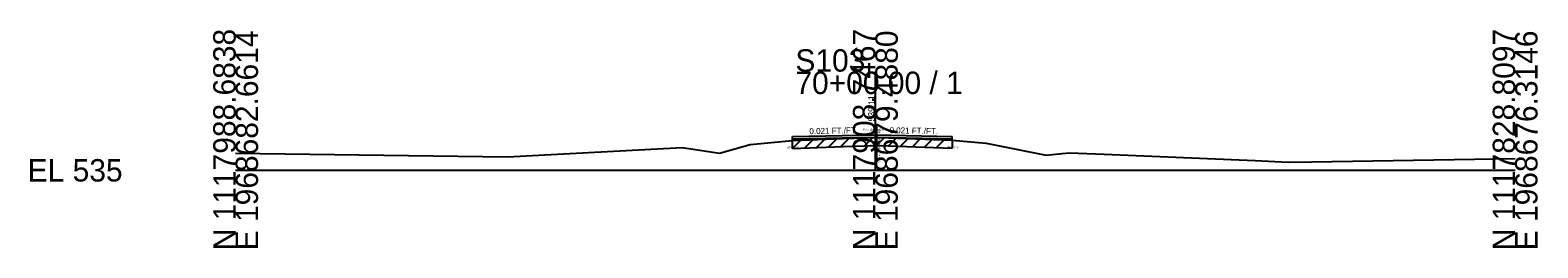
# Model space of a CAD drawing. Extents: x -26 to 163, y -10 to 24018.
# Drawn here: x -25.7 to 162.8, y 17990.3 to 18017.5 of the extents above; entities that cross this region are included whole.
import ezdxf

# ---------------------------------------------------------------- set-up
doc = ezdxf.new("R2010")
doc.units = 0
for name, color, linetype in [('RD_GPK_XS_Cell', 7, 'Continuous'), ('RD_XS_ExGround', 7, 'Continuous'), ('RD_XS_ExPaveRet', 7, 'Continuous'), ('RD_XS_Misc_Line', 7, 'Continuous'), ('RD_XS_PaveOvlay_CP', 7, 'Continuous'), ('RD_XS_TX_Elev_EX', 7, 'Continuous'), ('RD_XS_TX_ExEOP', 7, 'Continuous'), ('RD_XS_TX_Notes', 7, 'Continuous'), ('RD_XS_TX_Profile', 7, 'Continuous'), ('RD_XS_TX_Slope', 7, 'Continuous')]:
    doc.layers.add(name, color=color, linetype=linetype)

msp = doc.modelspace()

# ---------------------------------------------------------------- linework, layer by layer
at = {"layer": 'RD_GPK_XS_Cell'}
for p, q in [((80, 18000), (80, 18012.34)), ((0, 18000), (80, 18000)), ((80, 18000), (160, 18000))]:
    msp.add_line(p, q, dxfattribs=at)
at = {"layer": 'RD_XS_ExGround'}
msp.add_lwpolyline([(0, 18002.15), (33.98, 18001.68), (55.86, 18002.84), (60.51, 18002.13), (64.34, 18003.21), (69.63, 18003.74), (75.97, 18003.96), (80.14, 18004.11), (81.66, 18004.06), (89.61, 18003.77), (93.87, 18003.39), (101.36, 18001.89), (103.33, 18002.1), (104.26, 18002.2), (108.59, 18002.02), (127.49, 18001.22), (131.62, 18001.04), (134.56, 18001.08), (160, 18001.47)], dxfattribs=at)
at = {"layer": 'RD_XS_ExPaveRet'}
for p, q in [((69.63, 18002.74), (70.67, 18003.78)), ((69.63, 18002.74), (69.63, 18003.74)), ((71.13, 18002.79), (72.17, 18003.83)), ((72.63, 18002.85), (73.67, 18003.88)), ((74.13, 18002.9), (75.17, 18003.94)), ((75.63, 18002.95), (76.67, 18003.99)), ((75.97, 18002.96), (80.14, 18003.11)), ((77.13, 18003.01), (78.17, 18004.04)), ((78.63, 18003.06), (79.67, 18004.1)), ((80.13, 18003.11), (81.1, 18004.08)), ((80.14, 18003.11), (81.66, 18003.06)), ((81.63, 18003.06), (82.6, 18004.03)), ((81.66, 18003.06), (89.61, 18002.77)), ((83.13, 18003.01), (84.1, 18003.97)), ((84.63, 18002.95), (85.6, 18003.92)), ((86.13, 18002.9), (87.1, 18003.86)), ((87.63, 18002.84), (88.6, 18003.81)), ((89.61, 18003.77), (89.61, 18002.77)), ((69.63, 18002.74), (75.97, 18002.96))]:
    msp.add_line(p, q, dxfattribs=at)
at = {"layer": 'RD_XS_Misc_Line'}
msp.add_line((80.14, 18004.11), (80.14, 18001.11), dxfattribs=at)
at = {"layer": 'RD_XS_PaveOvlay_CP'}
for p, q in [((69.63, 18004.22), (80, 18004.44)), ((69.63, 18003.74), (69.63, 18004.22)), ((80, 18004.11), (69.63, 18003.89)), ((80, 18004.44), (89.61, 18004.24)), ((89.61, 18003.91), (80, 18004.11)), ((89.61, 18003.77), (89.61, 18004.24))]:
    msp.add_line(p, q, dxfattribs=at)

# ---------------------------------------------------------------- texts
at = {"layer": 'RD_GPK_XS_Cell'}
for s, p in [('N 1117988.6838', (0, 17990)), ('E 1968682.6614', (2.8, 17990)), ('N 1117908.7467', (80, 17990)), ('E 1968679.4880', (82.8, 17990)), ('N 1117828.8097', (160, 17990)), ('E 1968676.3146', (162.8, 17990))]:
    msp.add_text(s, height=2.8, rotation=90, dxfattribs=at).set_placement(p)
for s, p in [('S103', (70, 18012.34)), ('70+00.00 / 1', (70, 18009.54)), ('EL 535', (-26, 17998.6))]:
    msp.add_text(s, height=2.8, dxfattribs=at).set_placement(p)
at = {"layer": 'RD_XS_TX_Elev_EX'}
msp.add_text('539.11', height=0.8, rotation=90, dxfattribs=at).set_placement((79.9, 18006.11))
at = {"layer": 'RD_XS_TX_ExEOP'}
for s, p in [('EOP-L', (69.58, 18004.22)), ('EOP-R', (89.56, 18004.24))]:
    msp.add_text(s, height=0.1, rotation=270, dxfattribs=at).set_placement(p)
at = {"layer": 'RD_XS_TX_Notes'}
for s, p in [('Elev. @CL = 539.44', (78.47, 18004.94)), (' dE= 0.48', (68.92, 18002.74)), (' dE= 0.33', (79.29, 18003.11)), (' dE= 0.46', (88.89, 18002.77))]:
    msp.add_text(s, height=0.25, dxfattribs=at).set_placement(p)
msp.add_text(' Min. Distance @CP = -0.01', height=0.25, rotation=270, dxfattribs=at).set_placement((80.39, 18005.2))
at = {"layer": 'RD_XS_TX_Profile'}
msp.add_text('CL', height=0.25, dxfattribs=at).set_placement((79.77, 18004.44))
at = {"layer": 'RD_XS_TX_Slope'}
for rotation, p in [(1.1916, (71.76, 18004.52)), (358.8084, (81.76, 18004.65))]:
    msp.add_text('0.021 FT./FT.', height=0.75, rotation=rotation, dxfattribs=at).set_placement(p)

doc.saveas('drawing.dxf')
